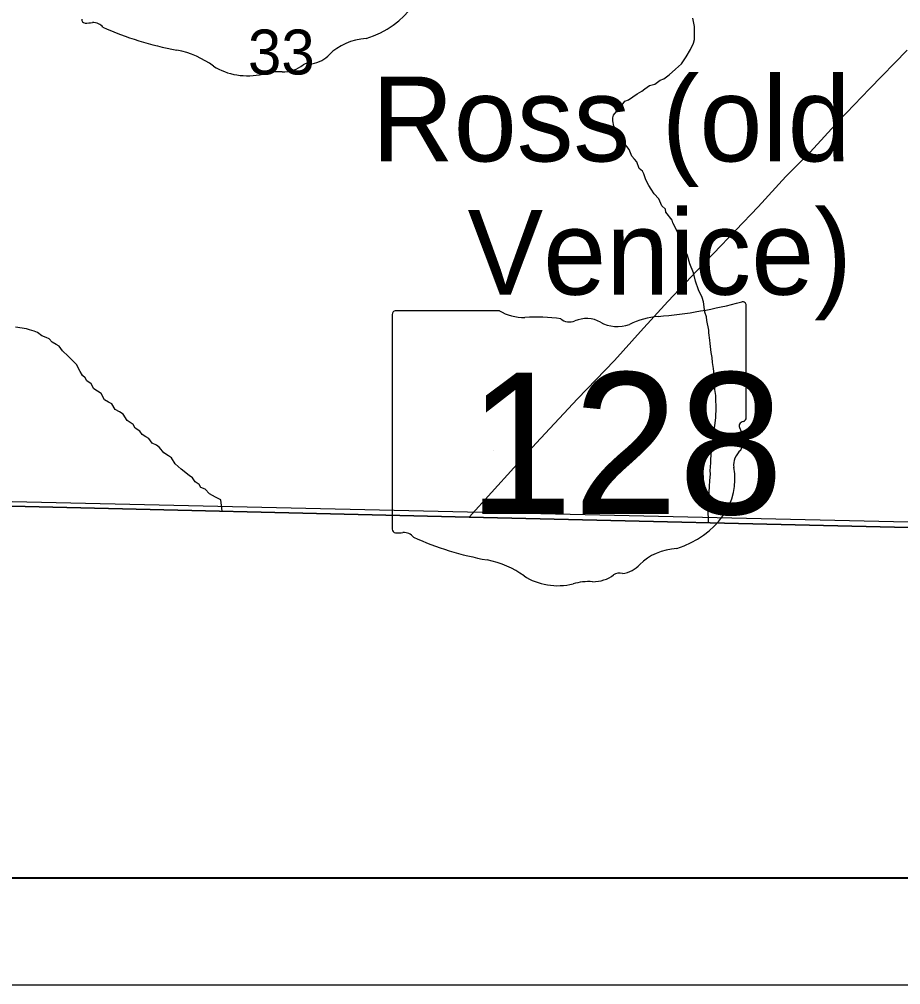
# Model space of a CAD drawing. Extents: x 0 to 34, y -2.3 to 22.
# Drawn here: x 4.399 to 5.22, y 14 to 14.899 of the extents above; entities that cross this region are included whole.
import ezdxf

# ---------------------------------------------------------------- set-up
doc = ezdxf.new("R2010")
doc.units = 0
for name, color, linetype in [('GM_X_Adjacent_County', 7, 'Continuous'), ('GM_X_County', 7, 'Continuous'), ('GM_X_Minor_River', 7, 'Continuous'), ('GM_X_Section', 7, 'Continuous'), ('GM_X_Section_Text', 7, 'Continuous'), ('GM_X_State_Location', 7, 'Continuous'), ('GM_X_State_Route', 7, 'Continuous'), ('GM_X_State_Shield', 7, 'Continuous'), ('GM_X_Township', 7, 'Continuous'), ('GM_X_Unincorporated_Text', 7, 'Continuous'), ('SH_Data', 7, 'Continuous')]:
    doc.layers.add(name, color=color, linetype=linetype)

msp = doc.modelspace()

# ---------------------------------------------------------------- linework, layer by layer
at = {"layer": 'GM_X_Adjacent_County'}
for p, q in [((4.81792, 14.43566), (3.27064, 14.47191)), ((5.27728, 14.42487), (4.81792, 14.43566)), ((2.07917, 14.09939), (8.87917, 14.09939))]:
    msp.add_line(p, q, dxfattribs=at)
at = {"layer": 'GM_X_County'}
for p, q in [((3.27064, 14.47191), (4.81792, 14.43566)), ((4.81792, 14.43566), (5.27728, 14.42487))]:
    msp.add_line(p, q, dxfattribs=at)
at = {"layer": 'GM_X_Minor_River'}
for p, q in [((5.02757, 14.89251), (5.02628, 14.90052)), ((5.02774, 14.88528), (5.02757, 14.89251)), ((5.0276, 14.88035), (5.02774, 14.88528)), ((5.02392, 14.87134), (5.02674, 14.87695)), ((5.02674, 14.87695), (5.0276, 14.88035)), ((5.01992, 14.86424), (5.02392, 14.87134)), ((5.01008, 14.85276), (5.01555, 14.85791)), ((5.01555, 14.85791), (5.01992, 14.86424)), ((5.00423, 14.84761), (5.01008, 14.85276)), ((4.9857, 14.83753), (4.99068, 14.8389)), ((4.99068, 14.8389), (4.99572, 14.84255)), ((4.99572, 14.84255), (4.99919, 14.84396)), ((4.99919, 14.84396), (5.00423, 14.84761)), ((4.97019, 14.82698), (4.97445, 14.82989)), ((4.97445, 14.82989), (4.97871, 14.83242)), ((4.97871, 14.83242), (4.98143, 14.83462)), ((4.98143, 14.83462), (4.9857, 14.83753)), ((4.9585, 14.81707), (4.96285, 14.82302)), ((4.96285, 14.82302), (4.96631, 14.82443)), ((4.96631, 14.82443), (4.97019, 14.82698)), ((4.95221, 14.81003), (4.95497, 14.81337)), ((4.95497, 14.81337), (4.9585, 14.81707)), ((4.95168, 14.80473), (4.95176, 14.80739)), ((4.95268, 14.79977), (4.95168, 14.80473)), ((4.95176, 14.80739), (4.95221, 14.81003)), ((4.95523, 14.79589), (4.95268, 14.79977)), ((4.95664, 14.79205), (4.95523, 14.79589)), ((4.95918, 14.78817), (4.95664, 14.79205)), ((4.96247, 14.78352), (4.95918, 14.78817)), ((4.96688, 14.77806), (4.96247, 14.78352)), ((4.96936, 14.77191), (4.96688, 14.77806)), ((4.97194, 14.76917), (4.96936, 14.77191)), ((4.97414, 14.76645), (4.97194, 14.76917)), ((4.97625, 14.76031), (4.97414, 14.76645)), ((4.97922, 14.75794), (4.97625, 14.76031)), ((4.98066, 14.75524), (4.97922, 14.75794)), ((4.98241, 14.74986), (4.98066, 14.75524)), ((4.98529, 14.74446), (4.98241, 14.74986)), ((4.98747, 14.74098), (4.98529, 14.74446)), ((4.99001, 14.73672), (4.98747, 14.74098)), ((4.99444, 14.73203), (4.99001, 14.73672)), ((4.99729, 14.72549), (4.99444, 14.73203)), ((5.00062, 14.72235), (4.99729, 14.72549)), ((5.00092, 14.71968), (5.00062, 14.72235)), ((5.00679, 14.71228), (5.00092, 14.71968)), ((5.00747, 14.7096), (5.00679, 14.71228)), ((5.01252, 14.69996), (5.00747, 14.7096)), ((5.01646, 14.69148), (5.01252, 14.69996)), ((5.0182, 14.68611), (5.01646, 14.69148)), ((5.02104, 14.67918), (5.0182, 14.68611)), ((5.02348, 14.67151), (5.02104, 14.67918)), ((5.02666, 14.66306), (5.02348, 14.67151)), ((5.02872, 14.6554), (5.02666, 14.66306)), ((5.03153, 14.64734), (5.02872, 14.6554)), ((5.03474, 14.64002), (5.03153, 14.64734)), ((5.03614, 14.63618), (5.03474, 14.64002)), ((5.03739, 14.62665), (5.03614, 14.63618)), ((5.03878, 14.62204), (5.03739, 14.62665)), ((5.03906, 14.61862), (5.03878, 14.62204)), ((5.04109, 14.60982), (5.03906, 14.61862)), ((4.40557, 14.61097), (4.39535, 14.61241)), ((4.4082, 14.61013), (4.40557, 14.61097)), ((4.41273, 14.60885), (4.4082, 14.61013)), ((4.41573, 14.60763), (4.41273, 14.60885)), ((4.41982, 14.60446), (4.41573, 14.60763)), ((5.04101, 14.60716), (5.04109, 14.60982)), ((5.04195, 14.60029), (5.04101, 14.60716)), ((4.42396, 14.60282), (4.41982, 14.60446)), ((4.42658, 14.6016), (4.42396, 14.60282)), ((4.42953, 14.59847), (4.42658, 14.6016)), ((4.43328, 14.59646), (4.42953, 14.59847)), ((4.43589, 14.59487), (4.43328, 14.59646)), ((5.04225, 14.59725), (5.04195, 14.60029)), ((5.04314, 14.58886), (5.04225, 14.59725)), ((4.43919, 14.59059), (4.43589, 14.59487)), ((4.44436, 14.58549), (4.43919, 14.59059)), ((5.04415, 14.58427), (5.04314, 14.58886)), ((4.45212, 14.57766), (4.44436, 14.58549)), ((5.0444, 14.57971), (5.04415, 14.58427)), ((5.04537, 14.57398), (5.0444, 14.57971)), ((4.45535, 14.57111), (4.45212, 14.57766)), ((4.45753, 14.56762), (4.45535, 14.57111)), ((5.04626, 14.56521), (5.04537, 14.57398)), ((4.46012, 14.56527), (4.45753, 14.56762)), ((4.46157, 14.56257), (4.46012, 14.56527)), ((4.46567, 14.55978), (4.46157, 14.56257)), ((5.04679, 14.55722), (5.04626, 14.56521)), ((4.46819, 14.55515), (4.46567, 14.55978)), ((4.47155, 14.55277), (4.46819, 14.55515)), ((4.47491, 14.55077), (4.47155, 14.55277)), ((5.04671, 14.55456), (5.04679, 14.55722)), ((5.04769, 14.54883), (5.04671, 14.55456)), ((4.47816, 14.54497), (4.47491, 14.55077)), ((4.4819, 14.54258), (4.47816, 14.54497)), ((4.48489, 14.54097), (4.4819, 14.54258)), ((5.04761, 14.54618), (5.04769, 14.54883)), ((5.04774, 14.53743), (5.04761, 14.54618)), ((4.48817, 14.53594), (4.48489, 14.54097)), ((4.49228, 14.53353), (4.48817, 14.53594)), ((4.49564, 14.53153), (4.49228, 14.53353)), ((5.04748, 14.52832), (5.04774, 14.53743)), ((4.49927, 14.52573), (4.49564, 14.53153)), ((4.50486, 14.52176), (4.49927, 14.52573)), ((5.0465, 14.52076), (5.04748, 14.52832)), ((4.50666, 14.51829), (4.50486, 14.52176)), ((4.51114, 14.51549), (4.50666, 14.51829)), ((4.51333, 14.51239), (4.51114, 14.51549)), ((5.04507, 14.51092), (5.04603, 14.51773)), ((5.04603, 14.51773), (5.0465, 14.52076)), ((4.5167, 14.51039), (4.51333, 14.51239)), ((4.51931, 14.50879), (4.5167, 14.51039)), ((4.52261, 14.50451), (4.51931, 14.50879)), ((5.044, 14.49993), (5.04498, 14.5075)), ((5.04498, 14.5075), (5.04507, 14.51092)), ((4.52673, 14.50249), (4.52261, 14.50451)), ((4.52934, 14.50051), (4.52673, 14.50249)), ((4.53337, 14.49545), (4.52934, 14.50051)), ((5.04293, 14.48933), (5.04354, 14.49729)), ((5.04354, 14.49729), (5.044, 14.49993)), ((4.53785, 14.49266), (4.53337, 14.49545)), ((4.54046, 14.49068), (4.53785, 14.49266)), ((4.5441, 14.48525), (4.54046, 14.49068)), ((5.04284, 14.48629), (5.04293, 14.48933)), ((4.54965, 14.48015), (4.5441, 14.48525)), ((4.55708, 14.47423), (4.54965, 14.48015)), ((5.04224, 14.47871), (5.04284, 14.48629)), ((4.56007, 14.47224), (4.55708, 14.47423)), ((4.56262, 14.46836), (4.56007, 14.47224)), ((5.04197, 14.46922), (5.04255, 14.47604)), ((5.04255, 14.47604), (5.04224, 14.47871)), ((4.56635, 14.46597), (4.56262, 14.46836)), ((4.56779, 14.46327), (4.56635, 14.46597)), ((4.57193, 14.46163), (4.56779, 14.46327)), ((4.57598, 14.45733), (4.57193, 14.46163)), ((5.04128, 14.4586), (5.04183, 14.46429)), ((5.04183, 14.46429), (5.04197, 14.46922)), ((4.58159, 14.45412), (4.57598, 14.45733)), ((4.58646, 14.4517), (4.58159, 14.45412)), ((5.04029, 14.45066), (5.04077, 14.45406)), ((5.04077, 14.45406), (5.04128, 14.4586)), ((4.58775, 14.44125), (4.58646, 14.4517)), ((5.04056, 14.44685), (5.04029, 14.45066)), ((5.04046, 14.44343), (5.04056, 14.44685)), ((5.0408, 14.43063), (5.04046, 14.44343))]:
    msp.add_line(p, q, dxfattribs=at)
at = {"layer": 'GM_X_Section'}
msp.add_line((5.2785, 14.42965), (4.26795, 14.45274), dxfattribs=at)
at = {"layer": 'GM_X_State_Route'}
for p, q in [((5.19065, 14.83468), (5.22575, 14.87065)), ((5.16216, 14.80489), (5.19065, 14.83468)), ((5.1354, 14.77545), (5.16216, 14.80489)), ((5.1129, 14.75282), (5.1354, 14.77545)), ((5.08688, 14.72459), (5.1129, 14.75282)), ((5.06607, 14.70299), (5.08688, 14.72459)), ((5.04552, 14.68115), (5.06607, 14.70299)), ((5.0303, 14.66528), (5.04552, 14.68115)), ((5.00299, 14.63653), (5.0303, 14.66528)), ((4.97736, 14.60843), (5.00299, 14.63653)), ((4.95313, 14.58142), (4.97736, 14.60843)), ((4.91887, 14.54581), (4.95313, 14.58142)), ((4.8803, 14.5046), (4.91887, 14.54581)), ((4.81792, 14.43566), (4.8803, 14.5046))]:
    msp.add_line(p, q, dxfattribs=at)
at = {"layer": 'GM_X_State_Shield'}
for p, q in [((5.07583, 14.52815), (5.07583, 14.63284)), ((4.74624, 14.62444), (4.74624, 14.42432)), ((4.84601, 14.62788), (4.74949, 14.62788)), ((5.0758, 14.52818), (5.07583, 14.52815))]:
    msp.add_line(p, q, dxfattribs=at)
for centre, major_axis, start_param, end_param in [((4.68884, 14.94603), (0.08742, 0), 5.101752, 6.440018), ((4.46089, 14.89888), (0.00385, 0), 3.00124, 4.508301), ((4.46147, 14.91935), (0.0294, 0), 4.665946, 4.897461), ((4.46749, 14.88777), (0.0106, 0), 0.519207, 1.627899), ((4.60131, 15.06757), (0.2524, 0), 4.195997, 4.488961), ((4.7257, 14.84313), (0.04788, 0), 1.647645, 2.488434), ((4.52606, 14.80941), (0.07897, 0), 0.823519, 1.323587), ((4.66504, 14.87992), (0.02824, 0), 4.937069, 5.64225), ((4.64409, 14.87179), (0.0267, 0), 4.691044, 5.507374), ((4.66824, 14.85241), (0.00752, 0), 1.147584, 2.315152), ((4.61147, 14.88678), (0.05011, 0), 4.026481, 4.996735), ((4.64043, 14.81759), (0.04118, 0), 1.495662, 1.94098), ((4.95842, 14.90071), (0.34952, 0), 4.814394, 5.042369), ((5.07217, 14.63327), (0.00367, 0), 6.141152, 7.989035), ((4.75002, 14.62486), (0.00382, 0), 1.712693, 3.28349), ((4.869, 14.65111), (0.03703, 0), 4.042523, 4.731795), ((4.88127, 14.51553), (0.13295, 0), 1.404758, 1.657858), ((4.91146, 14.6259), (0.01068, 0), 3.836095, 5.185415), ((4.92714, 14.60277), (0.02221, 0), 0.950623, 2.079405), ((4.95581, 14.6345), (0.02672, 0), 4.081561, 5.145723), ((5.00301, 14.56676), (0.07032, 0), 1.699011, 2.107814), ((5.07498, 14.52047), (0.00568, 0), 1.883978, 3.671073), ((5.07191, 14.52775), (0.00393, 0), 5.05454, 6.418171), ((5.03886, 14.50724), (0.03409, 0), 5.934695, 6.695948), ((5.08897, 14.48434), (0.0248, 0), 2.387724, 3.262537), ((4.978, 14.47103), (0.08742, 0), 5.101752, 6.440018), ((4.75005, 14.42388), (0.00385, 0), 3.00124, 4.508301), ((4.75064, 14.44435), (0.0294, 0), 4.665946, 4.897461), ((4.75665, 14.41277), (0.0106, 0), 0.519207, 1.627899), ((4.89048, 14.59257), (0.2524, 0), 4.195997, 4.488961), ((5.01487, 14.36813), (0.04788, 0), 1.647645, 2.488434), ((4.81523, 14.33441), (0.07897, 0), 0.823519, 1.323587), ((4.9542, 14.40492), (0.02824, 0), 4.937069, 5.64225), ((4.90064, 14.41178), (0.05011, 0), 4.026481, 4.996735), ((4.93326, 14.39679), (0.0267, 0), 4.691044, 5.507374), ((4.95741, 14.37741), (0.00752, 0), 1.147584, 2.315152), ((4.92959, 14.34259), (0.04118, 0), 1.495662, 1.94098)]:
    msp.add_ellipse(centre, major_axis=major_axis, ratio=0.8, start_param=start_param, end_param=end_param, dxfattribs=at)
at = {"layer": 'GM_X_Township'}
for p, q in [((4.81792, 14.43566), (3.27064, 14.47191)), ((5.27728, 14.42487), (4.81792, 14.43566))]:
    msp.add_line(p, q, dxfattribs=at)
at = {"layer": 'SH_Data'}
for p, q in [((2.1, 14.1), (8.9, 14.1)), ((2, 14), (9, 14))]:
    msp.add_line(p, q, dxfattribs=at)

# ---------------------------------------------------------------- texts
at = {"layer": 'GM_X_Section_Text'}
msp.add_text('33', height=0.041856, rotation=0.00001, dxfattribs=at).set_placement((4.61172, 14.8479))
at = {"layer": 'GM_X_State_Location'}
for s in ['s', 'r']:
    msp.add_text(s, height=0.000189, dxfattribs=at).set_placement((4.90733, 14.51107))
msp.add_text('128', height=0.000189, rotation=0.00001, dxfattribs=at).set_placement((4.84047, 14.49729))
at = {"layer": 'GM_X_State_Shield'}
msp.add_text('128', height=0.131836, dxfattribs=at).set_placement((4.81652, 14.43843))
at = {"layer": 'GM_X_Unincorporated_Text'}
for s, p in [('Ross (old', (4.72714, 14.76697)), ('Venice)', (4.81631, 14.6428))]:
    msp.add_text(s, height=0.078977, rotation=0.00001, dxfattribs=at).set_placement(p)

doc.saveas('drawing.dxf')
